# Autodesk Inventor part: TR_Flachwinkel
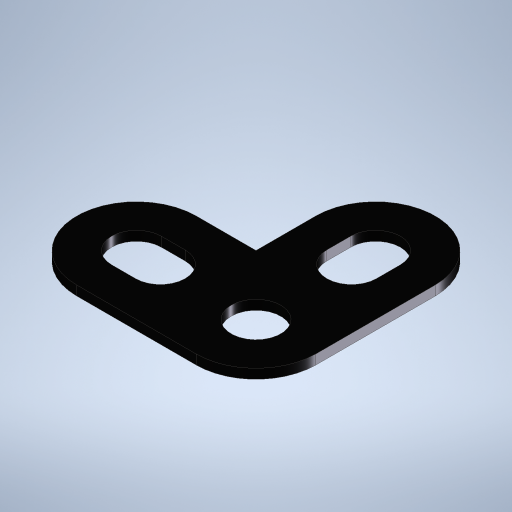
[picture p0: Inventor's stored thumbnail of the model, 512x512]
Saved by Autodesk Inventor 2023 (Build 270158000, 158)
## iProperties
Created: 2023-11
Part Number: TR_Flachwinkel
Material: Edelstahl
Document SubType Name: Modeling
Designer: Admin
Density: 8 g/cm^3
Appearance: Halbpoliert
Author: Admin
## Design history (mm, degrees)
sketch "Skizze1"
  geometry: L1 (0, 5)-(10, 5); L2 (10, -5)-(5, -5); L3 (5, -5)-(5, -10); L4 (-5, -10)-(-5, 0); L5 (10, 0)-(8, 0); L6 (10, 2.075)-(8, 2.075); L7 (8, -2.075)-(10, -2.075); L8 (0, -10)-(0, -8); L9 (2.075, -10)-(2.075, -8); L10 (-2.075, -8)-(-2.075, -10); C1 r 2.075 at (0, 0); A1 r 5 centre (0, 0) between (0, 5) and (-5, 0); A2 r 5 centre (10, 0) between (10, -5) and (10, 5); A3 r 5 centre (0, -10) between (-5, -10) and (5, -10); A4 r 2.075 centre (10, 0) between (10, -2.075) and (10, 2.075); A5 r 2.075 centre (8, 0) between (8, 2.075) and (8, -2.075); A6 r 2.075 centre (0, -10) between (-2.075, -10) and (2.075, -10); A7 r 2.075 centre (0, -8) between (2.075, -8) and (-2.075, -8); 3 further points
  constraints: 24 end point, 14 point on circle, 14 tangent, 8 centre point, 3 horizontal, 3 perpendicular, 2 coincident, 2 midpoint, 2 parallel, 2 vertical alignment, 1 equal radius, 1 horizontal alignment, 1 vertical
  dimensions: "d0" = 5 radius of A2 (= 0.5 x Einheitsmaß); "d1" = 10 distance of L8.start point (0, 0) (= Einheitsmaß); "d2" = 4.15 diameter of C1 (= 2 x Radius); "d3" = 2 distance of L5.start L5.end (= Breitloch); "d4" = 4.15 diameter of A5 (= 2 x Radius); "d5" = 2 distance of L8.start L8.end (= Breitloch); "d6" = 4.15 diameter of A7 (= 2 x Radius)
extrude "Extrusion1" new body sketch "Skizze1" distance "d7" = 0.8 (= Dicke); taper "d8" = 0 deg
node "Volumenkörper1"
other parameters: "Einheitsmaß" = 10 [user parameter; used in 2 equation terms], "Radius" = 2.075 [user parameter; used in 3 equation terms], "Fasen" = 0.5 [user parameter], "Dicke" = 0.8 [user parameter; used in 1 equation term], "Breitloch" = 2 [user parameter; used in 2 equation terms], "Langloch" = 32 [user parameter]
